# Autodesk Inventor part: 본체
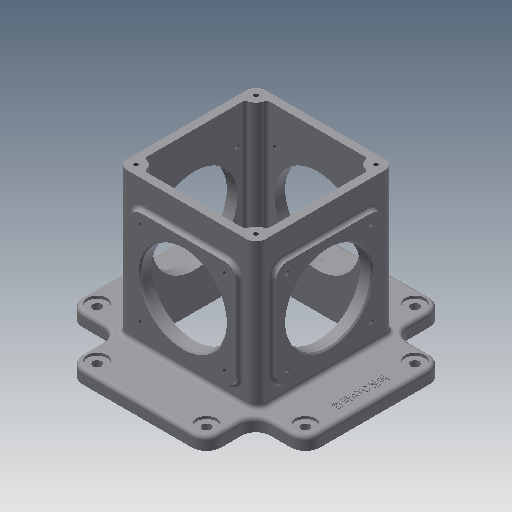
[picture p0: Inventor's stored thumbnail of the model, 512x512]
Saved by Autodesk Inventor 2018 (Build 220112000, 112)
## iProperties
Created: 2018-09
Part Number: 본체
Material: 일반
Document SubType Name: Modeling
Designer: mduedu
Density: 1 g/cm^3
Appearance: 기본값
Author: mduedu
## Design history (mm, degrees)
sketch "스케치1"
  geometry: L1 (90, 52.5)-(-90, 52.5); L2 (-90, 52.5)-(-90, -52.5); L3 (-90, -52.5)-(90, -52.5); L4 (90, -52.5)-(90, 52.5); L5 (90, 52.5)-(-90, -52.5); L6 (-90, 52.5)-(90, -52.5); L7 (-52.5, -90)-(52.5, -90); L8 (52.5, -90)-(52.5, 90); L9 (52.5, 90)-(-52.5, 90); L10 (-52.5, 90)-(-52.5, -90); L11 (-52.5, -90)-(52.5, 90); L12 (52.5, -90)-(-52.5, 90); 1 further point
  constraints: 24 end point, 4 midpoint, 4 parallel, 2 horizontal, 2 perpendicular
  dimensions: "d0" = 180 distance of L3.end L2.end; "d1" = 105 distance of L2.end L1.end; "d105" = 105 distance of L9.end L8.end; "d106" = 180 distance of L8.end L7.end
extrude "돌출1" new body sketch "스케치1" distance "d2" = 10; taper "d3" = 0 deg
fillet "모깎기16" dims "d107" = 11
sketch "스케치2"
  geometry: L1 (-52.5, -52.5)-(52.5, -52.5); L2 (52.5, -52.5)-(52.5, 52.5); L3 (52.5, 52.5)-(-52.5, 52.5); L4 (-52.5, 52.5)-(-52.5, -52.5); L5 (-52.5, -52.5)-(52.5, 52.5); L6 (52.5, -52.5)-(-52.5, 52.5); 1 further point
  constraints: 12 end point, 2 midpoint, 2 parallel, 1 horizontal, 1 perpendicular
  dimensions: "d4" = 105 distance of L3.end L2.end; "d5" = 105 distance of L2.end L1.end
extrude "돌출2" join sketch "스케치2" distance "d6" = 110; taper "d7" = 0 deg
sketch "스케치14"
  geometry: L1 (-52.5, 52.5)-(52.5, 52.5) reference; L2 (52.5, 52.5)-(52.5, -52.5) reference; L3 (52.5, -52.5)-(-52.5, -52.5) reference; L4 (-52.5, -52.5)-(-52.5, 52.5) reference; L5 (46.5, 46.5)-(-46.5, 46.5); L6 (-46.5, 46.5)-(-46.5, -46.5); L7 (-46.5, -46.5)-(46.5, -46.5); L8 (46.5, -46.5)-(46.5, 46.5); 1 further point
  constraints: 8 end point, 3 other
  dimensions: "d85" = 6 distance between parallel lines of L5 L1
extrude "돌출10" cut sketch "스케치14" extent not by distance; stored distance "d86" = 10; taper "d87" = 0 deg
fillet "모깎기1" dims "d12" = 7
sketch "스케치15"
  geometry: A1 r 7 centre (-45.5, 45.5) between (-45.5, 52.5) and (-52.5, 45.5) reference; A2 r 7 centre (45.5, 45.5) between (52.5, 45.5) and (45.5, 52.5) reference; A3 r 7 centre (45.5, -45.5) between (45.5, -52.5) and (52.5, -45.5) reference; A4 r 7 centre (-45.5, -45.5) between (-52.5, -45.5) and (-45.5, -52.5) reference; 5 further points
  constraints: 4 coincident, 4 vertical alignment, 8 other
extrude "돌출11" join sketch "스케치15" stored distance "d88" = 10; taper "d89" = 0 deg
fillet "모깎기15" dims "d90" = 3
sketch "스케치6"
  geometry: L1 (50, 20)-(130, 20); L2 (130, 20)-(130, 100); L3 (130, 100)-(50, 100); L4 (50, 100)-(50, 20); L5 (50, 20)-(130, 100); L6 (130, 20)-(50, 100); L7 (0, 0)-(180, 0) reference; 4 further points
  constraints: 12 end point, 4 midpoint, 2 parallel, 1 horizontal, 1 perpendicular, 1 vertical alignment
  dimensions: "d25" = 80 distance of L3.end L2.end; "d26" = 80 distance of L2.end L1.end; "d27" = 60 distance of point (90, 0) point (90, 60)
extrude "돌출6" join sketch "스케치6" distance "d28" = 3; taper "d29" = 0 deg
fillet "모깎기7" dims "d30" = 8
sketch "스케치7"
  geometry: C1 r 32.5 at (90, 60); 1 further point
  constraints: 1 centre point, 1 vertical alignment
  dimensions: "d32" = 65 diameter of C1; "d33" = 60 distance of C1.centre point (90, 0)
extrude "돌출7" cut sketch "스케치7" stored distance "d34" = 3; taper "d35" = 0 deg
fillet "모깎기9" dims "d36" = 3
sketch "스케치8"
  geometry: L1 (5.5, 10)-(85.5, 10); L2 (85.5, 10)-(85.5, 90); L3 (85.5, 90)-(5.5, 90); L4 (5.5, 90)-(5.5, 10); L5 (5.5, 10)-(85.5, 90); L6 (85.5, 10)-(5.5, 90); L7 (-7, -10)-(98, -10) reference; C1 r 32.5 at (45.5, 50); 4 further points
  constraints: 12 end point, 4 midpoint, 2 parallel, 1 centre point, 1 coincident, 1 horizontal, 1 perpendicular, 1 vertical alignment
  dimensions: "d37" = 80 distance of L3.end L2.end; "d38" = 80 distance of L2.end L1.end; "d39" = 60 distance from line of point (45.5, 50) L7; "d40" = 65 diameter of C1
extrude "돌출8" join sketch "스케치8" distance "d41" = 3; taper "d42" = 0 deg
fillet "모깎기10" dims "d43" = 8
extrude "돌출9" cut sketch "스케치8" stored distance "d44" = 3; taper "d45" = 0 deg
fillet "모깎기11" dims "d46" = 3
sketch "스케치9"
  geometry: L1 (50, 92)-(50, 28) reference; L2 (58, 20)-(122, 20) reference; L3 (130, 28)-(130, 92) reference; L4 (122, 100)-(58, 100) reference; C1 r 32.5 at (90, 60) reference; A1 r 8 centre (58, 92) between (58, 100) and (50, 92) reference; A2 r 8 centre (58, 28) between (50, 28) and (58, 20) reference; A3 r 8 centre (122, 28) between (122, 20) and (130, 28) reference; A4 r 8 centre (122, 92) between (130, 92) and (122, 100) reference; 5 further points
  constraints: 4 coincident
hole "구멍1" sketch "스케치9" at (58, 92), (122, 92), (122, 28), (58, 28) diameter "d47" = 3.242; stored, may be unused: countersink angle "d51" = 90 deg, drill point angle "d53" = 118 deg; dims "d48" = 6, "d49" = 4, "d50" = 2, "d52" = 9
sketch "스케치10"
  geometry: L1 (13.5, 10)-(77.5, 10) reference; L2 (85.5, 18)-(85.5, 82) reference; L3 (77.5, 90)-(13.5, 90) reference; L4 (5.5, 82)-(5.5, 18) reference; C1 r 32.5 at (45.5, 50) reference; A1 r 8 centre (13.5, 18) between (5.5, 18) and (13.5, 10) reference; A2 r 8 centre (77.5, 18) between (77.5, 10) and (85.5, 18) reference; A3 r 8 centre (77.5, 82) between (85.5, 82) and (77.5, 90) reference; A4 r 8 centre (13.5, 82) between (13.5, 90) and (5.5, 82) reference; 5 further points
  constraints: 4 coincident
hole "구멍2" sketch "스케치10" at (13.5, 82), (77.5, 82), (77.5, 18), (13.5, 18) diameter "d54" = 3.242; stored, may be unused: countersink angle "d58" = 90 deg, drill point angle "d60" = 118 deg; dims "d55" = 6, "d56" = 4, "d57" = 2, "d59" = 9
fillet "모깎기12" dims "d68" = 11
sketch "스케치16"
  geometry: A1 r 11 centre (-79, 41.5) between (-79, 52.5) and (-90, 41.5) reference; A2 r 11 centre (-79, -41.5) between (-90, -41.5) and (-79, -52.5) reference; A3 r 11 centre (79, 41.5) between (90, 41.5) and (79, 52.5) reference; A4 r 11 centre (79, -41.5) between (79, -52.5) and (90, -41.5) reference; A5 r 11 centre (-41.5, 79) between (-41.5, 90) and (-52.5, 79) reference; A6 r 11 centre (41.5, 79) between (52.5, 79) and (41.5, 90) reference; A7 r 11 centre (41.5, -79) between (41.5, -90) and (52.5, -79) reference; A8 r 11 centre (-41.5, -79) between (-52.5, -79) and (-41.5, -90) reference; 9 further points
  constraints: 8 coincident
hole "구멍5" sketch "스케치16" at (-79, 41.5), (79, 41.5), (79, -41.5), (-79, -41.5), (41.5, 79), (-41.5, 79), (-41.5, -79), (41.5, -79) diameter "d91" = 6.6; stored, may be unused: countersink angle "d95" = 90 deg, drill point angle "d97" = 118 deg; dims "d92" = 6, "d93" = 15, "d94" = 2, "d96" = 8
fillet "모깎기13" dims "d77" = 3
chamfer "모따기1" distance "d79" = 1; stored, may be unused: second distance "d80" = 2, angle "d81" = 45 deg
sketch "스케치17"
  geometry: A1 r 7 centre (-45.5, 45.5) between (-45.5, 52.5) and (-52.5, 45.5) reference; A2 r 7 centre (-45.5, -45.5) between (-52.5, -45.5) and (-45.5, -52.5) reference; A3 r 7 centre (45.5, -45.5) between (45.5, -52.5) and (52.5, -45.5) reference; A4 r 7 centre (45.5, 45.5) between (52.5, 45.5) and (45.5, 52.5) reference; 5 further points
  constraints: 4 coincident
hole "구멍6" sketch "스케치17" at (-45.5, 45.5), (45.5, 45.5), (45.5, -45.5), (-45.5, -45.5) diameter "d98" = 3.242; stored, may be unused: countersink angle "d102" = 90 deg, drill point angle "d104" = 118 deg; dims "d99" = 8, "d100" = 15, "d101" = 2, "d103" = 10
sketch "스케치13"
  geometry: L1 (90, -41.5)-(90, 41.5) reference; 2 further points
  constraints: 1 horizontal alignment, 1 other
  dimensions: "d82" = 11 distance from line of point (79, 0) L1
feature "엠보싱1" sketch "스케치13" dims "d0" = 180, "d1" = 105, "d83" = 0.5, "d84" = 0
node "솔리드1"
mirror "대칭1"
mirror "대칭4"
mirror "대칭2"
mirror "대칭5"
node "투영된 루프2"
node "투영된 루프3"
node "투영된 루프6"
